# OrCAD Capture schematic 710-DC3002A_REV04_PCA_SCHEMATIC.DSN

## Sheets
1 LT8625SP: size B; note: 18V, 8A MONOLITHIC SYNCHRONOUS STEP-DOWN
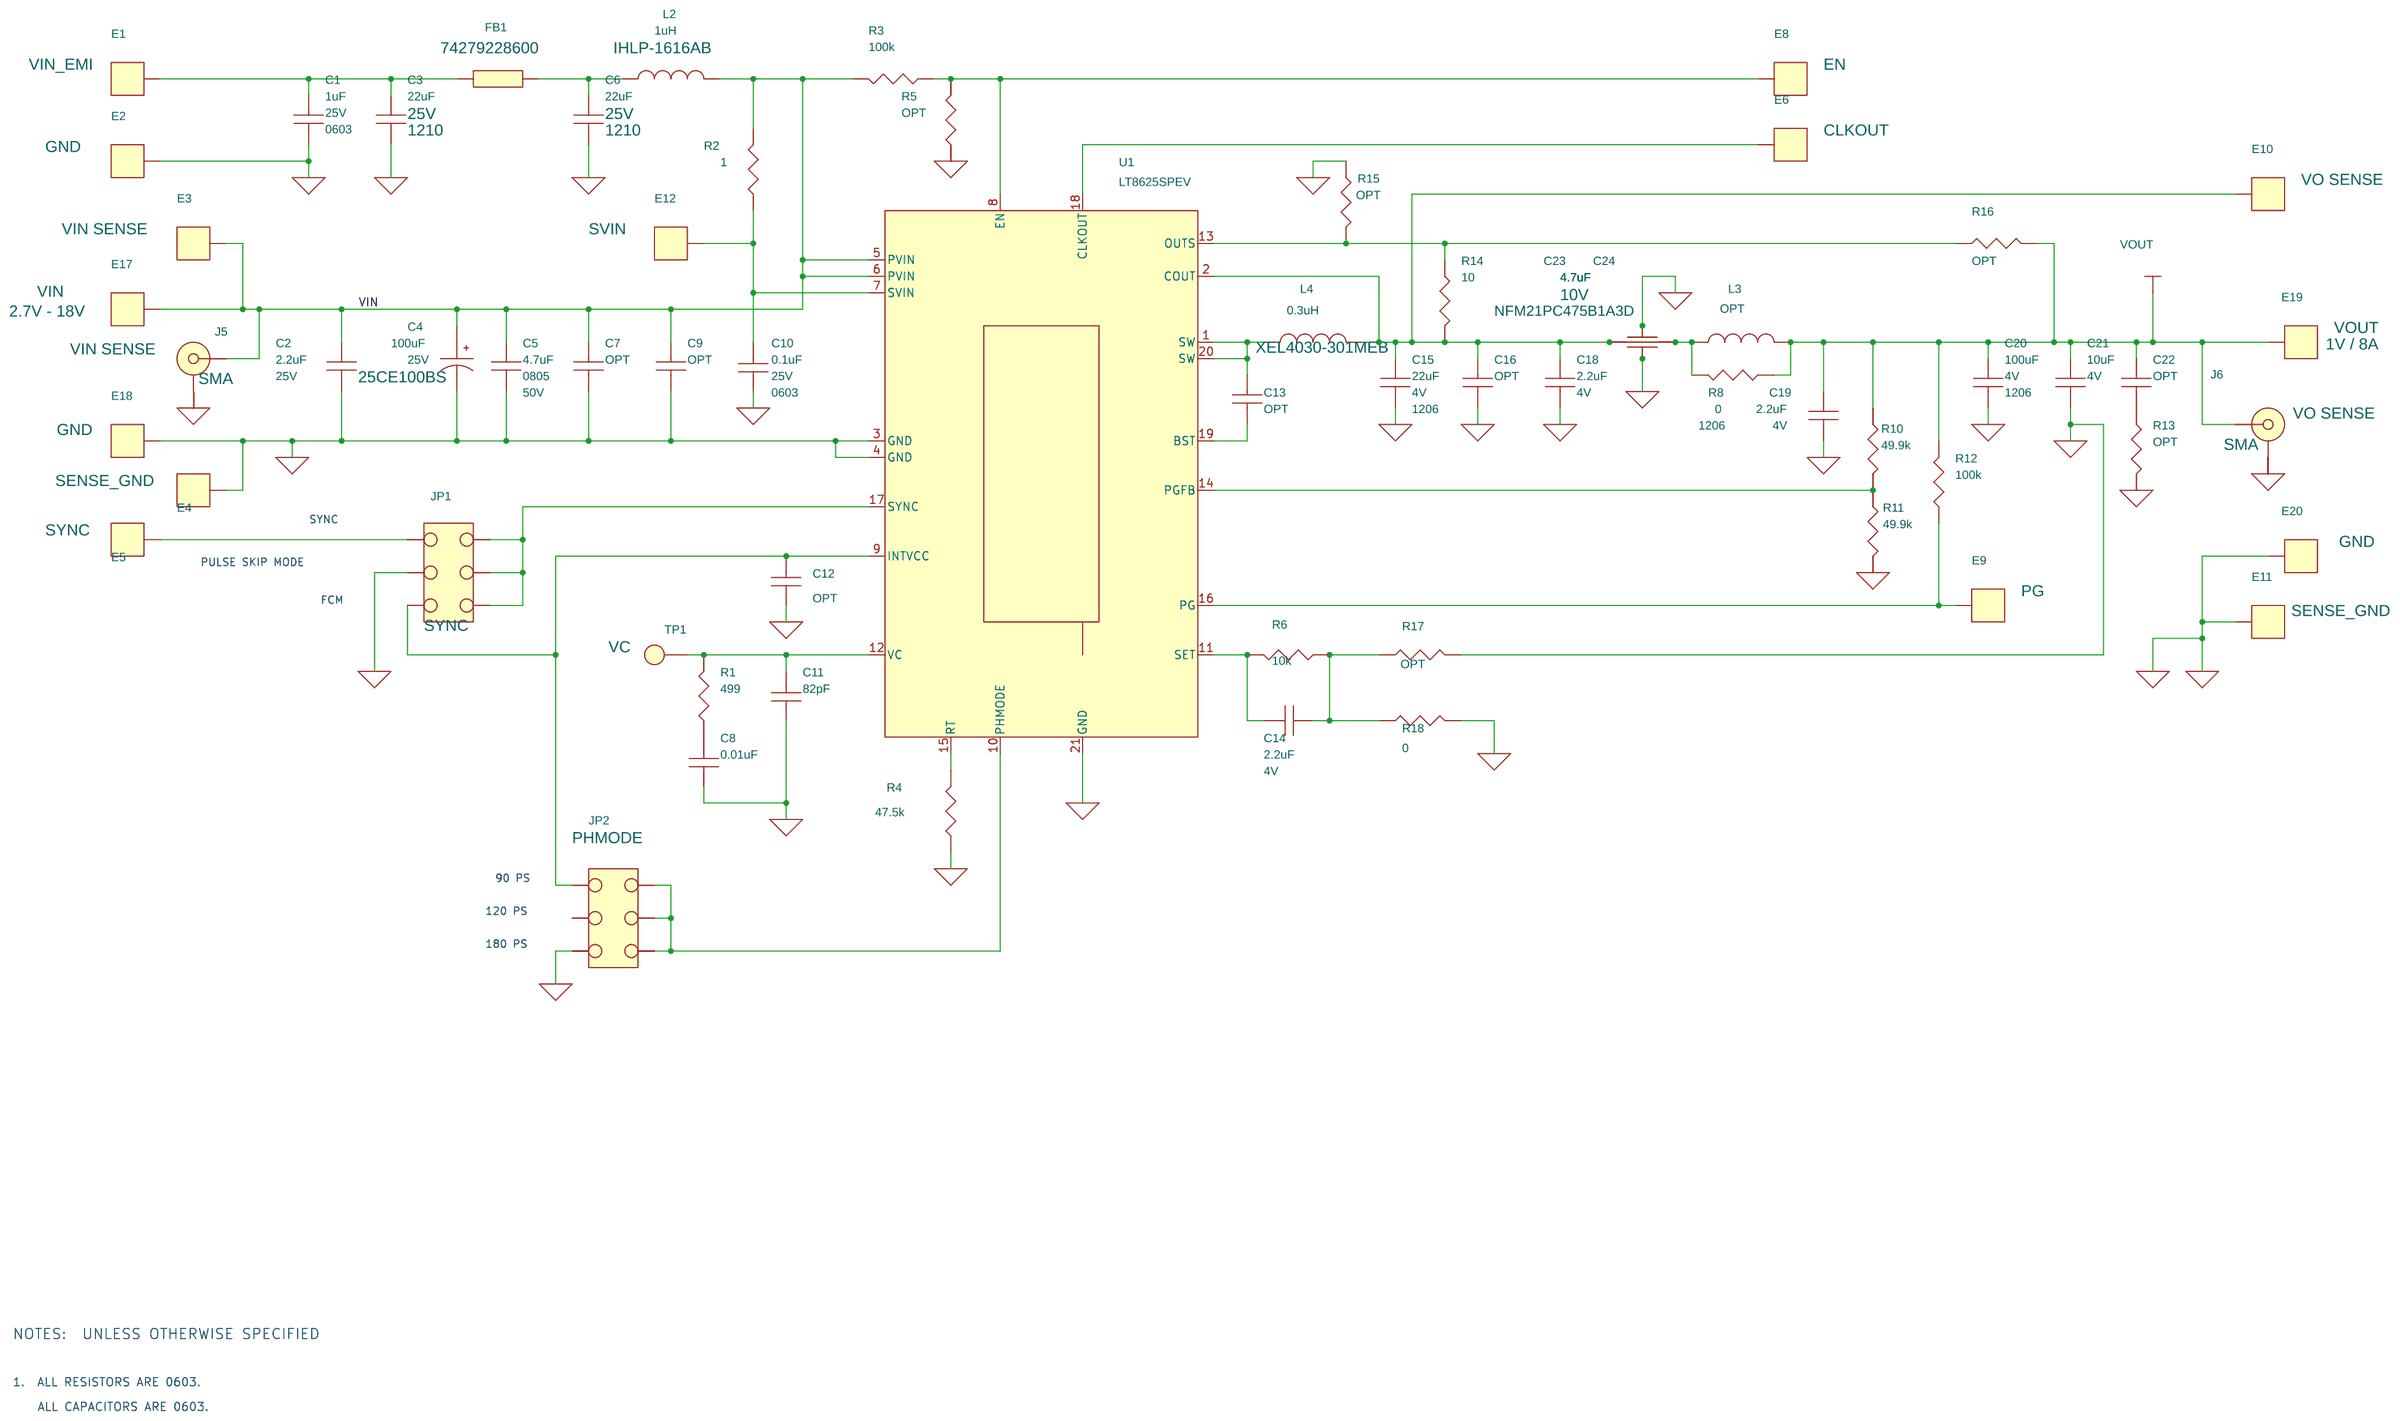
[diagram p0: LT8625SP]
2 HARDWARE
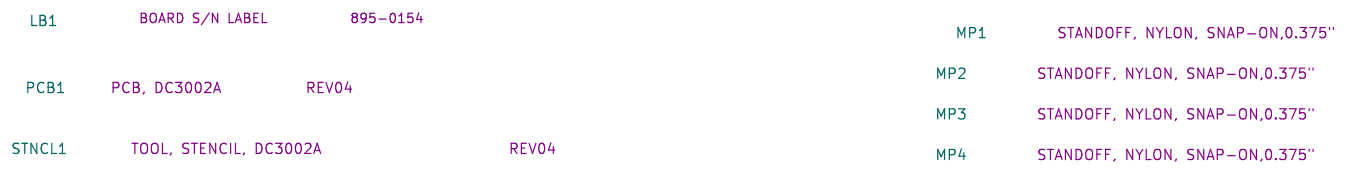
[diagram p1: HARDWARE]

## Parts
sheet HARDWARE
LB1  LABEL  [895-0154_REV01]
MP1  STANDOFF, NYLON, SNAP-ON  [KEYSTONE_8829-8834]
MP2  STANDOFF, NYLON, SNAP-ON  [KEYSTONE_8829-8834]
MP3  STANDOFF, NYLON, SNAP-ON  [KEYSTONE_8829-8834]
MP4  STANDOFF, NYLON, SNAP-ON  [KEYSTONE_8829-8834]
PCB1  PCB, DC3002A
STNCL1  TOOL, STENCIL, DC3002A
sheet LT8625SP
C1  1uF  [CC0603N]
C2  2.2uF  [CC0603N]
C3  22uF  [CC1210N]
C4  100uF  [SUNCON_CE-BS_6.3X7.7]
C5  4.7uF  [CC0805N]
C6  22uF  [CC1210N]
C7  OPT  [CC0603N]
C8  0.01uF  [CC0603N]
C9  OPT  [CC0603N]
C10  0.1uF  [CC0603N]
C11  82pF  [CC0603N]
C12  OPT  [CC0603N]
C13  OPT  [CC0603N]
C14  2.2uF  [CC0603N]
C15  22uF  [CC1206N]
C16  OPT  [CC0603N]
C18  2.2uF  [CC0603N]
C19  2.2uF  [CC0603N]
C20  100uF  [CC1206N]
C21  10uF  [CC0603N]
C22  OPT  [CC0603N]
C23  4.7uF  [MURATA-NFM21]
C24  4.7uF  [MURATA-NFM21]
E1  TEST POINT  [HARWIN_S2751-46R]
E2  TEST POINT  [HARWIN_S2751-46R]
E3  TEST POINT  [HARWIN_S2751-46R]
E4  TEST POINT  [HARWIN_S2751-46R]
E5  TEST POINT  [HARWIN_S2751-46R]
E6  TEST POINT  [HARWIN_S2751-46R]
E8  TEST POINT  [HARWIN_S2751-46R]
E9  TEST POINT  [HARWIN_S2751-46R]
E10  TEST POINT  [HARWIN_S2751-46R]
E11  TEST POINT  [HARWIN_S2751-46R]
E12  TEST POINT  [HARWIN_S2751-46R]
E17  TEST POINT  [KEYSTONE_5019]
E18  TEST POINT  [KEYSTONE_5019]
E19  TEST POINT  [KEYSTONE_5019]
E20  TEST POINT  [KEYSTONE_5019]
FB1  60 OHMS@100MHz  [IND0603N]
J5  RF/COAX,SMA JACK  [MOLEX-732511350]
J6  RF/COAX,SMA JACK  [MOLEX-732511350]
JP1  HDR  [HD2X3-079]
JP2  HDR  [HD2X3-079]
L2  1uH  [VISHAY-IHLP-1616AB-01]
L3  OPT  [COILCRAFT-XEL4030]
L4  0.3uH  [COILCRAFT-XEL4030]
R1  499  [CR0603N]
R2  1  [CR0603N]
R3  100k  [CR0603N]
R4  47.5k  [CR0603N]
R5  OPT  [CR0603N]
R6  10k  [CR0603N]
R8  0  [CR1206N]
R10  49.9k  [CR0603N]
R11  49.9k  [CR0603N]
R12  100k  [CR0603N]
R13  OPT  [CR0603N]
R14  10  [CR0603N]
R15  OPT  [CR0603N]
R16  OPT  [CR0603N]
R17  OPT  [CR0603N]
R18  0  [CR0603N]
TP1  TEST PAD  [PADSTYLE1]
U1  LT8625SPEV  [LTC-LQFN-20-1602]
XJP1  SHUNT
XJP2  SHUNT

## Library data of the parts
LB1 = BLANK_LABEL: LABEL SPEC, DEMO BOARD SERIAL NUMBER; Inventory Qty: 0; Manufacturer: BRADY; Manufacturer PN: THT-96-717-10; PART_FIELD_01: BOARD S/N LABEL; PART_NUMBER: 895-0154
MP1-MP4 = BLANK_PINLESS_MECHANICAL_PART: STANDOFF, NYLON, SNAP-ON,0.375"; CLASS: DISCRETE; FPLIST: KEYSTONE_8829-8834,KEYSTONE_8832; Inventory Qty: 202920; Manufacturer: KEYSTONE; Manufacturer PN: 8832; PART_NUMBER: 763-0008
PCB1 = BLANK_PCB_PART: BOM Notes: REV04; CLASS: DISCRETE; Inventory Qty: 0; Manufacturer: ADI APPROVED SUPPLIER; Manufacturer PN: 600-DC3002A; PART_NUMBER: 600-DC3002A
STNCL1 = BLANK_STENCIL_PART: BOM Notes: REV04; CLASS: DISCRETE; Inventory Qty: 0; Manufacturer: ADI APPROVED SUPPLIER; Manufacturer PN: 830-DC3002A; PART_NUMBER: 830-DC3002A
C1 = CAP: CAP.,1uF,X7R,25V,10%,0603; CLASS: DISCRETE; Dielectric Type: X7R; FPLIST: CC0603N,CC0603L,CC0603M; Inventory Qty: 47828; Manufacturer: MURATA; Manufacturer PN: GRM188R71E105KA12D; PART_NUMBER: 150-3372; Package Size: 0603; Package Type: SMD; Rated Voltage: 25V; Tolerance: 10%
C2 = CAP: CAP.,2.2uF,X7S,25V,10%,0603; CLASS: DISCRETE; Dielectric Type: X7S; FPLIST: CC0603N,CC0603L,CC0603M; Inventory Qty: 20000; Manufacturer: MURATA; Manufacturer PN: GRM188C71E225KE11D; PART_NUMBER: 150-1812; Package Size: 0603; Rated Voltage: 25V; Temperature Coefficient: X7S; Tolerance: 10%
C3 C6 = CAP: CAP.,22uF,X7R,25V,10%,1210; CLASS: DISCRETE; Dielectric Type: X7R; FPLIST: CC1210N,CC1210L,CC1210M; Inventory Qty: 28580; Manufacturer: AVX; Manufacturer PN: 12103C226KAT2A; PART_NUMBER: 150-3343; Package Size: 1210; Rated Voltage: 25V; Tolerance: 10%
C4 = CAP_P_ALT: CAP.,100uF,ALUM ELECT,25V,20%,6.3x7.7mm,CE-BS Series; CLASS: DISCRETE; Dielectric Type: ALUM ELECT; Inventory Qty: 0; Manufacturer: SUN ELECTRONIC INDUSTRIES CORP; Manufacturer PN: 25CE100BS; PART_NUMBER: 150-1793; Package Size: 6.3x7.7mm; Rated Voltage: 25V; Tolerance: 20%
C5 = CAP: CAP.,4.7uF,X7S,50V,10%,0805; CLASS: DISCRETE; Dielectric Type: X7S; FPLIST: CC0805N,CC0805L,CC0805M; Inventory Qty: 0; Manufacturer: MURATA; Manufacturer PN: GRM21BC71H475KE11K; PART_NUMBER: 150-1287; Package Size: 0805; Rated Voltage: 50V; Tolerance: 10%
C7 C9 C12 C13 C16 C22 = CAP: CAP., OPTION, 0603; CLASS: DISCRETE; FPLIST: CC0603N,CC0603L,CC0603M; PART_NUMBER: 150-3038; Package Size: 0603; Package Type: SMD
C8 = CAP: CAP.,0.01uF,X7R,50V,10%,0603; CLASS: DISCRETE; Dielectric Type: X7R; FPLIST: CC0603N,CC0603L,CC0603M; Inventory Qty: 28283; Manufacturer: AVX; Manufacturer PN: 06035C103KAT2A; PART_NUMBER: 150-0002; Package Size: 0603; Rated Voltage: 50V; Tolerance: 10%
C10 = CAP: CAP.,0.1uF,X7R,25V,10%,0603; CLASS: DISCRETE; Dielectric Type: X7R; FPLIST: CC0603N,CC0603L,CC0603M; Inventory Qty: 60590; Manufacturer: AVX; Manufacturer PN: 06033C104KAT2A; PART_NUMBER: 150-0065; Package Size: 0603; Rated Voltage: 25V; Tolerance: 10%
C11 = CAP: CAP.,82pF,X7R,50V,10%,0603; CLASS: DISCRETE; Dielectric Type: X7R; FPLIST: CC0603N,CC0603L,CC0603M; Inventory Qty: 0; Manufacturer: KEMET; Manufacturer PN: C0603C820K5RAC7867; PART_NUMBER: 150-1854; Package Size: 0603; Rated Voltage: 50V; Tolerance: 10%
C14 C18 C19 = CAP: CAP.,2.2uF,X7S,4V,10%,0603; CLASS: DISCRETE; Dielectric Type: X7S; FPLIST: CC0603N,CC0603L,CC0603M; Inventory Qty: 8000; Manufacturer: TDK; Manufacturer PN: CGB3B1X7S0G225K055AC; PART_NUMBER: 150-1815; Package Size: 0603; Rated Voltage: 4V; Temperature Coefficient: X7S; Tolerance: 10%
C15 = CAP: CAP.,22uF,X7R,4V,10%,1206,AEC-Q200; CLASS: DISCRETE; Dielectric Type: X7R; FPLIST: CC1206N,CC1206L,CC1206M; Inventory Qty: 0; Manufacturer: Taiyo Yuden; Manufacturer PN: AMK316AB7226KLHT; PART_NUMBER: 150-1855; Package Size: 1206; Rated Voltage: 4V; Tolerance: 10%
C20 = CAP: CAP.,100uF,X5R,4V,20%,1206; CLASS: DISCRETE; Dielectric Type: X5R; FPLIST: CC1206N,CC1206L,CC1206M; Inventory Qty: 2000; Manufacturer: MURATA; Manufacturer PN: GRM31CR60G107ME39L; PART_NUMBER: 150-1738; Package Size: 1206; Rated Voltage: 4V; Tolerance: 20%
C21 = CAP: CAP.,10uF,X7S,4V,20%,0603; CLASS: DISCRETE; Dielectric Type: X7S; FPLIST: CC0603N,CC0603L,CC0603M; Inventory Qty: 4000; Manufacturer: TDK; Manufacturer PN: C1608X7S0G106M080AB; PART_NUMBER: 150-1816; Package Size: 0603; Rated Voltage: 4V; Temperature Coefficient: X7S; Tolerance: 20%
C23 C24 = CAPACITOR_3_TERM: CAP.,4.7uF,FEEDTHRU,10V,20%,0805,3-TERM,SMD,EMI FILTER,6A; CLASS: DISCRETE; Dielectric Type: FEEDTHRU; Inventory Qty: 10140; Manufacturer: MURATA; Manufacturer PN: NFM21PC475B1A3D; PART_NUMBER: 150-2473; Package Size: 0805,3-TERM,SMD; Package Type: Surface Mount; Rated Voltage: 10V; Tolerance: 20%
E1 = MP-PINNED: TEST POINT,BRASS CONTACT,TIN PLATING,2.00 x 1.20 x 1.40mm,VERT,SMT,NATURAL; 10th Part Field: VIN_EMI; CLASS: DISCRETE; Inventory Qty: 14260; Manufacturer: HARWIN; Manufacturer PN: S2751-46R; PART_NUMBER: 260-0017; Package Size: 0.079" L x 0.047" W
E2 = MP-PINNED: TEST POINT,BRASS CONTACT,TIN PLATING,2.00 x 1.20 x 1.40mm,VERT,SMT,NATURAL; 10th Part Field: GND; CLASS: DISCRETE; Inventory Qty: 14260; Manufacturer: HARWIN; Manufacturer PN: S2751-46R; PART_NUMBER: 260-0017; Package Size: 0.079" L x 0.047" W
E3 = MP-PINNED: TEST POINT,BRASS CONTACT,TIN PLATING,2.00 x 1.20 x 1.40mm,VERT,SMT,NATURAL; 10th Part Field: VIN SENSE; CLASS: DISCRETE; Inventory Qty: 14260; Manufacturer: HARWIN; Manufacturer PN: S2751-46R; PART_NUMBER: 260-0017; Package Size: 0.079" L x 0.047" W
E4 = MP-PINNED: TEST POINT,BRASS CONTACT,TIN PLATING,2.00 x 1.20 x 1.40mm,VERT,SMT,NATURAL; 10th Part Field: SENSE_GND; 9th Part Field: 1.5V - 18V; CLASS: DISCRETE; Inventory Qty: 14260; Manufacturer: HARWIN; Manufacturer PN: S2751-46R; PART_NUMBER: 260-0017; Package Size: 0.079" L x 0.047" W
E5 = MP-PINNED: TEST POINT,BRASS CONTACT,TIN PLATING,2.00 x 1.20 x 1.40mm,VERT,SMT,NATURAL; 10th Part Field: SYNC; 9th Part Field: 1.5V - 18V; CLASS: DISCRETE; Inventory Qty: 14260; Manufacturer: HARWIN; Manufacturer PN: S2751-46R; PART_NUMBER: 260-0017; Package Size: 0.079" L x 0.047" W
E6 = MP-PINNED: TEST POINT,BRASS CONTACT,TIN PLATING,2.00 x 1.20 x 1.40mm,VERT,SMT,NATURAL; 10th Part Field: CLKOUT; CLASS: DISCRETE; Inventory Qty: 14260; Manufacturer: HARWIN; Manufacturer PN: S2751-46R; PART_NUMBER: 260-0017; Package Size: 0.079" L x 0.047" W
E8 = MP-PINNED: TEST POINT,BRASS CONTACT,TIN PLATING,2.00 x 1.20 x 1.40mm,VERT,SMT,NATURAL; 10th Part Field: EN; CLASS: DISCRETE; Inventory Qty: 14260; Manufacturer: HARWIN; Manufacturer PN: S2751-46R; PART_NUMBER: 260-0017; Package Size: 0.079" L x 0.047" W
E9 = MP-PINNED: TEST POINT,BRASS CONTACT,TIN PLATING,2.00 x 1.20 x 1.40mm,VERT,SMT,NATURAL; 10th Part Field: PG; CLASS: DISCRETE; Inventory Qty: 14260; Manufacturer: HARWIN; Manufacturer PN: S2751-46R; PART_NUMBER: 260-0017; Package Size: 0.079" L x 0.047" W
E10 = MP-PINNED: TEST POINT,BRASS CONTACT,TIN PLATING,2.00 x 1.20 x 1.40mm,VERT,SMT,NATURAL; 10th Part Field: VO SENSE; CLASS: DISCRETE; Inventory Qty: 14260; Manufacturer: HARWIN; Manufacturer PN: S2751-46R; PART_NUMBER: 260-0017; Package Size: 0.079" L x 0.047" W
E11 = MP-PINNED: TEST POINT,BRASS CONTACT,TIN PLATING,2.00 x 1.20 x 1.40mm,VERT,SMT,NATURAL; 10th Part Field: SENSE_GND; CLASS: DISCRETE; Inventory Qty: 14260; Manufacturer: HARWIN; Manufacturer PN: S2751-46R; PART_NUMBER: 260-0017; Package Size: 0.079" L x 0.047" W
E12 = MP-PINNED: TEST POINT,BRASS CONTACT,TIN PLATING,2.00 x 1.20 x 1.40mm,VERT,SMT,NATURAL; 10th Part Field: SVIN; CLASS: DISCRETE; Inventory Qty: 14260; Manufacturer: HARWIN; Manufacturer PN: S2751-46R; PART_NUMBER: 260-0017; Package Size: 0.079" L x 0.047" W
E17 = MP-PINNED: TEST POINT,SILVER PLATE,PHOSPHOR BRONZE,3.81mmX2.03mm,2.29mm H,SMT; 10th Part Field: 2.7V - 18V; 9th Part Field: VIN; CLASS: DISCRETE; Inventory Qty: 40128; Manufacturer: KEYSTONE; Manufacturer PN: 5019; PART_NUMBER: 260-0018; Package Size: 0.15" L x 0.080" W
E18 E20 = MP-PINNED: TEST POINT,SILVER PLATE,PHOSPHOR BRONZE,3.81mmX2.03mm,2.29mm H,SMT; 10th Part Field: GND; 9th Part Field: GND; CLASS: DISCRETE; Inventory Qty: 40128; Manufacturer: KEYSTONE; Manufacturer PN: 5019; PART_NUMBER: 260-0018; Package Size: 0.15" L x 0.080" W
E19 = MP-PINNED: TEST POINT,SILVER PLATE,PHOSPHOR BRONZE,3.81mmX2.03mm,2.29mm H,SMT; 10th Part Field: 1V / 8A; 9th Part Field: VOUT; CLASS: DISCRETE; Inventory Qty: 40128; Manufacturer: KEYSTONE; Manufacturer PN: 5019; PART_NUMBER: 260-0018; Package Size: 0.15" L x 0.080" W
FB1 = FERRITEBEAD_ALT1: IND.,60 OHMS@100MHz,PWR,FERRITE BEAD,25%,5100mA,15mOHMS,0603; CLASS: DISCRETE; Inventory Qty: 0; Manufacturer: WURTH ELEKTRONIK; Manufacturer PN: 74279228600; PART_NUMBER: 200-0759; Package Size: 0603; Tolerance: 25%
J5 = COAX_CONN_5PIN_ALT1: CONN.,RF/COAX,SMA JACK,FEMALE,1PORT,VERT,ST,SMT,50 OHMS,Au; 10th Part Field: VIN SENSE; 9th Part Field: SMA; CLASS: IO; Inventory Qty: 2280; Manufacturer: MOLEX; Manufacturer PN: 0732511350; PART_NUMBER: 250-0959
J6 = COAX_CONN_5PIN_ALT1: CONN.,RF/COAX,SMA JACK,FEMALE,1PORT,VERT,ST,SMT,50 OHMS,Au; 10th Part Field: VO SENSE; 9th Part Field: SMA; CLASS: IO; Inventory Qty: 2280; Manufacturer: MOLEX; Manufacturer PN: 0732511350; PART_NUMBER: 250-0959
JP1 = HEADER_2X3_.079: CONN.,HDR,MALE,2x3,2mm,VERT,ST,THT; 9th Part Field: SYNC; CLASS: IO; FPLIST: HD2X3-079,WURTH-62000621121; Inventory Qty: 17651; Manufacturer: WURTH ELEKTRONIK; Manufacturer PN: 62000621121; PART_NUMBER: 250-0483
JP2 = HEADER_2X3_.079: CONN.,HDR,MALE,2x3,2mm,VERT,ST,THT; 9th Part Field: PHMODE; CLASS: IO; FPLIST: HD2X3-079,WURTH-62000621121; Inventory Qty: 17651; Manufacturer: WURTH ELEKTRONIK; Manufacturer PN: 62000621121; PART_NUMBER: 250-0483
L2 = IND_ALT: IND.,1uH,PWR,SHIELDED,20%,4A,52.5mOHMS,1616AB,IHLP-01 Series; 9th Part Field: IHLP-1616AB; CLASS: DISCRETE; Inventory Qty: 4500; Manufacturer: VISHAY; Manufacturer PN: IHLP1616ABER1R0M01; PART_NUMBER: 200-0760; Package Size: 1616AB; Tolerance: 20%
L3 = IND_ALT: IND., OPTION; CLASS: DISCRETE; Package Size: USER ASSIGNED
L4 = IND: IND.,0.3uH,PWR,SHIELDED,20%,18.9A,3.1mOhms,4.3x4.3mm,XEL4030,AEC-Q200; CLASS: DISCRETE; Inventory Qty: 0; Manufacturer: COILCRAFT; Manufacturer PN: XEL4030-301MEB; PART_NUMBER: 200-0598; Package Size: 4.3x4.3mm,XEL4030; Tolerance: 20%
R1 = RES: RES.,499 OHMS,1%,1/10W,0603,AEC-Q200; CLASS: DISCRETE; FPLIST: CR0603N,CR0603L,CR0603M; Inventory Qty: 19400; Manufacturer: VISHAY; Manufacturer PN: CRCW0603499RFKEA; PART_NUMBER: 100-2777; Package Size: 0603; Rated Power: 1/10W; Temperature Coefficient: 100ppm/C; Tolerance: 1%
R2 = RES: RES.,1 OHM,1%,1/10W,0603,AEC-Q200; CLASS: DISCRETE; FPLIST: CR0603N,CR0603L,CR0603M; Inventory Qty: 53360; Manufacturer: NIC; Manufacturer PN: NRC06F1R00TRF; PART_NUMBER: 100-0238; Package Size: 0603; Rated Power: 1/10W; Temperature Coefficient: 100ppm/C; Tolerance: 1%
R3 R12 = RES: RES.,100k OHMS,1%,1/10W,0603,AEC-Q200; CLASS: DISCRETE; FPLIST: CR0603N,CR0603L,CR0603M; Inventory Qty: 185604; Manufacturer: VISHAY; Manufacturer PN: CRCW0603100KFKEA; PART_NUMBER: 100-0343; Package Size: 0603; Rated Power: 1/10W; Temperature Coefficient: +/-100ppm; Tolerance: 1%
R4 = RES: RES.,47.5k OHMS,1%,1/10W,0603; CLASS: DISCRETE; FPLIST: CR0603N,CR0603L,CR0603M; Inventory Qty: 67863; Manufacturer: VISHAY; Manufacturer PN: CRCW060347K5FKEA; PART_NUMBER: 100-2554; Package Size: 0603; Rated Power: 1/10W; Temperature Coefficient: 100ppm/C; Tolerance: 1%
R5 R13 R15-R17 = RES: RES., OPTION, 0603; CLASS: DISCRETE; FPLIST: CR0603N,CR0603L,CR0603M; PART_NUMBER: 100-2374; Package Size: 0603
R6 = RES: RES.,10k OHMS,1%,1/10W,0603,AEC-Q200; CLASS: DISCRETE; FPLIST: CR0603N,CR0603L,CR0603M; Inventory Qty: 194448; Manufacturer: VISHAY; Manufacturer PN: CRCW060310K0FKEA; PART_NUMBER: 100-2012; Package Size: 0603; Rated Power: 1/10W; Temperature Coefficient: +/-100ppm/C; Tolerance: 1%
R8 = RES: RES.,0 OHM,3/4W,1206,PULSE PROOF,HIGH PWR,AEC-Q200; CLASS: DISCRETE; FPLIST: CR1206N,CR1206L,CR1206M; Inventory Qty: 21928; Manufacturer: VISHAY; Manufacturer PN: CRCW12060000Z0EAHP; PART_NUMBER: 100-2119; Package Size: 1206; Rated Power: 3/4W
R10 R11 = RES: RES.,49.9k OHMS,1%,1/10W,0603; CLASS: DISCRETE; FPLIST: CR0603N,CR0603L,CR0603M; Inventory Qty: 100527; Manufacturer: NIC; Manufacturer PN: NRC06F4992TRF; PART_NUMBER: 100-0303; Package Size: 0603; Rated Power: 1/10W; Temperature Coefficient: 100ppm/C; Tolerance: 1%
R14 = RES: RES.,10 OHMS,1%,1/10W,0603; CLASS: DISCRETE; FPLIST: CR0603N,CR0603L,CR0603M; Inventory Qty: 152750; Manufacturer: VISHAY; Manufacturer PN: CRCW060310R0FKEA; PART_NUMBER: 100-2306; Package Size: 0603; Rated Power: 1/10W; Temperature Coefficient: 100ppm/C; Tolerance: 1%
R18 = RES: RES.,0 OHM,1/10W,0603,AEC-Q200; CLASS: DISCRETE; FPLIST: CR0603N,CR0603L,CR0603M; Inventory Qty: 686486; Manufacturer: VISHAY; Manufacturer PN: CRCW06030000Z0EA; PART_NUMBER: 100-0009; Package Size: 0603; Rated Power: 1/10W
TP1 = PAD_STYLE_C: TESTPOINT, PCB COPPER FEATURE; 10th Part Field: VC; CLASS: IO; FPLIST: PADSTYLE1,PADSTYLE2,PADSTYLE3,PADSTYLE4,PADSTYLE5,PADSTYLE6,PADSTYLE7,PADSTYLE8; Manufacturer: N/A; Manufacturer PN: N/A
U1 = LT8625SP-LQFN: IC,Syn. Step-Down Silent Switcher,LQFN-20; CLASS: IC; Inventory Qty: 0; Manufacturer: ANALOG DEVICES; Manufacturer PN: LT8625SPEV#PBF; PART_NUMBER: LT8625SPEV#PBF; Package Type: LQFN-20
XJP1 XJP2 = SHUNT_2MM_C: CONN.,SHUNT,FEMALE,2-POS,2mm; CLASS: IO; Inventory Qty: 64675; Manufacturer: Wurth Elektronik; Manufacturer PN: 60800213421; PART_NUMBER: 250-0485

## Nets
GND: C1.2 C2.2 C3.2 C4.2 C5.2 C6.2 C7.2 C8.1 C9.2 C10.1 C11.1 C12.1 C15.2 C16.2 C18.2 C19.2 C20.2 C21.2 C23.2 C23.4 C24.2 C24.4 E2.1 E4.1 E11.1 E18.1 E20.1 J5.2 J5.3 J5.4 J5.5 J6.2 J6.3 J6.4 J6.5 JP1.3 JP2.5 R4.1 R5.2 R11.1 R13.2 R15.1 R17.2 R18.2 U1.3(GND) U1.4(GND) U1.21(GND)
VIN: C2.1 C4.1 C5.1 C7.1 C9.1 E3.1 E17.1 J5.1 L2.2 R2.1 R3.2 U1.5(PVIN) U1.6(PVIN)
VOUT: C19.1 C20.1 C21.1 C22.1 E19.1 J6.1 L3.2 R8.1 R10.2 R12.1 R16.1
N17263236: C11.2 R1.2 TP1.1 U1.12(VC)
N17263477: JP1.2 JP1.4 JP1.6 U1.17(SYNC)
N17263500: E5.1 JP1.1
N17263509: C12.2 JP1.5 JP2.1 U1.9(INTVCC)
N17265521: C1.1 C3.1 E1.1 FB1.1
N17265531: C6.1 FB1.2 L2.1
N17266354: E8.1 R3.1 R5.1 U1.8(EN)
N17268060: R4.2 U1.15(RT)
N17268975: E9.1 R12.2 U1.16(PG)
N17271151: C15.1 C16.1 C18.1 C23.1 C24.1 E10.1 L4.2 R14.2 U1.2(COUT)
N17271791: JP2.2 JP2.4 JP2.6 U1.10(PHMODE)
N17279966: C10.2 E12.1 R2.2 U1.7(SVIN)
N17284744: C14.2 R6.1 U1.11(SET)
N17284751: C14.1 R6.2 R17.1 R18.1
N17294738: C13.1 L4.1 U1.1(SW) U1.20(SW)
N17294971: E6.1 U1.18(CLKOUT)
N17296871: C23.3 C24.3 L3.1 R8.2
N17327079: C13.2 U1.19(BST)
N17329450: R10.1 R11.2 U1.14(PGFB)
N17334325: R14.1 R15.2 R16.2 U1.13(OUTS)
N17440553: C8.2 R1.1
N17440558: C22.2 R13.1

Not connected (* = marked no-connect by the designer): JP2 3

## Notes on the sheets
sheet 1
- SYNC
- PULSE SKIP MODE
- FCM
- 90 PS
- 120 PS
- 180 PS
- NOTES:  UNLESS OTHERWISE SPECIFIED
- 1.  ALL RESISTORS ARE 0603.
- ALL CAPACITORS ARE 0603.
